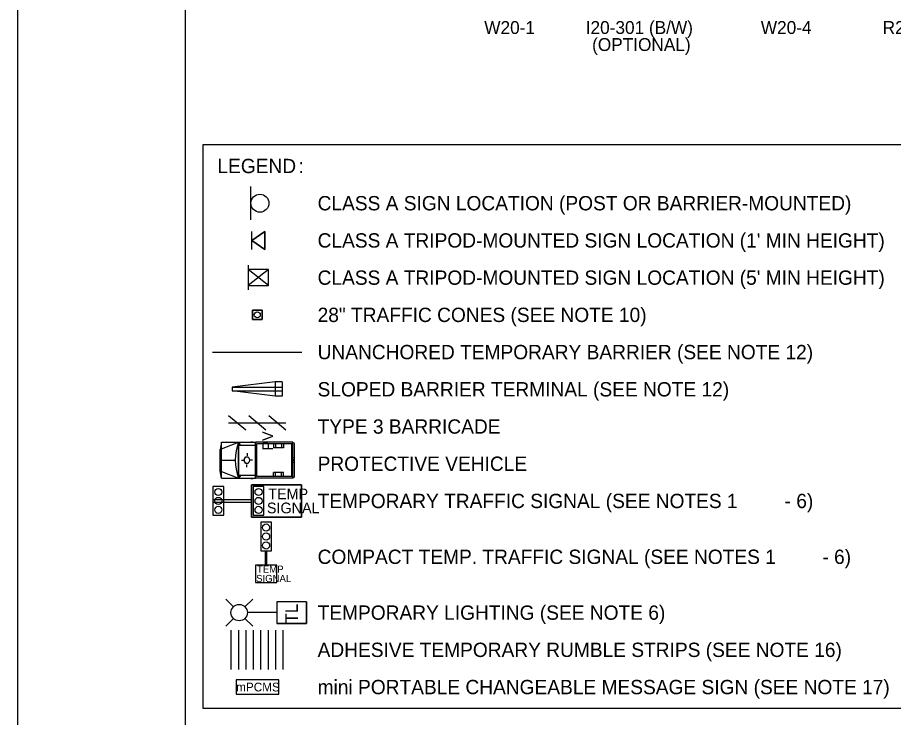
# Model space of a CAD drawing. Extents: x 99977 to 100176, y 99905 to 100011.
# Drawn here: x 99999.062 to 100003.959, y 99971.176 to 99975.088 of the extents above; entities that cross this region are included whole.
import ezdxf

# ---------------------------------------------------------------- set-up
doc = ezdxf.new("R2010")
doc.units = 0
for name, color, linetype in [('SH_GI_PlotLimits', 7, 'Continuous'), ('SH_GI_SheetBorder', 7, 'Continuous'), ('TR_SN_ConstructionSigns', 7, 'Continuous'), ('TR_WZ_BarricadeType3', 7, 'Continuous'), ('TR_WZ_BarrierTemp', 7, 'Continuous'), ('TR_WZ_PortableChangeMessageSign', 7, 'Continuous'), ('TR_WZ_PortableLightStandard', 7, 'Continuous'), ('TR_WZ_PortableSignMount5ftMinBlk-Wht', 7, 'Continuous'), ('TR_WZ_PortableSignMountBlk-Wht', 7, 'Continuous'), ('TR_WZ_ProtectiveVehicle', 7, 'Continuous'), ('TR_WZ_ScaleTerminalEndSection', 7, 'Continuous'), ('TR_WZ_Sign', 7, 'Continuous'), ('TR_WZ_TempSignal', 7, 'Continuous'), ('TR_WZ_TrafficCone', 7, 'Continuous'), ('TR_WZ_WorkZoneDetails', 7, 'Continuous'), ('TR_WZ_WorkZoneTextCurrent', 7, 'Continuous')]:
    doc.layers.add(name, color=color, linetype=linetype)

msp = doc.modelspace()

# ---------------------------------------------------------------- linework, layer by layer
at = {"layer": 'SH_GI_PlotLimits'}
msp.add_lwpolyline([(99999.0625, 99969.6875), (100016.0625, 99969.6875), (100016.0625, 99980.6875), (99999.0625, 99980.6875)], close=True, dxfattribs=at)
at = {"layer": 'SH_GI_SheetBorder'}
msp.add_line((100000, 99980.375), (100000, 99970), dxfattribs=at)
at = {"layer": 'TR_WZ_BarricadeType3'}
for p, q in [((100000.3381, 99972.7823), (100000.2425, 99972.8615)), ((100000.4503, 99972.7823), (100000.3547, 99972.8615)), ((100000.5625, 99972.7823), (100000.4669, 99972.8615)), ((100000.2425, 99972.8219), (100000.5625, 99972.8219))]:
    msp.add_line(p, q, dxfattribs=at)
at = {"layer": 'TR_WZ_BarrierTemp'}
msp.add_line((100000.1525, 99973.2179), (100000.6525, 99973.2179), dxfattribs=at)
at = {"layer": 'TR_WZ_PortableChangeMessageSign'}
msp.add_lwpolyline([(100000.2841, 99971.3059), (100000.5241, 99971.3059), (100000.5241, 99971.3859), (100000.2841, 99971.3859)], close=True, dxfattribs=at)
msp.add_lwpolyline([(100000.2841, 99971.3059), (100000.5241, 99971.3059), (100000.5241, 99971.3859), (100000.2841, 99971.3859), (100000.2841, 99971.3059)], dxfattribs=at)
at = {"layer": 'TR_WZ_PortableLightStandard'}
for p, q in [((100000.2692, 99971.7943), (100000.2261, 99971.8373)), ((100000.3339, 99971.7943), (100000.377, 99971.8373)), ((100000.6777, 99971.8219), (100000.5117, 99971.8219)), ((100000.5117, 99971.8219), (100000.5117, 99971.7019)), ((100000.6777, 99971.8219), (100000.5117, 99971.8219)), ((100000.6777, 99971.8219), (100000.6777, 99971.7019)), ((100000.2692, 99971.7295), (100000.2261, 99971.6864)), ((100000.3339, 99971.7295), (100000.377, 99971.6864)), ((100000.5117, 99971.7619), (100000.3473, 99971.7619)), ((100000.6777, 99971.7019), (100000.5117, 99971.7019)), ((100000.5117, 99971.7019), (100000.6777, 99971.7019))]:
    msp.add_line(p, q, dxfattribs=at)
for points in [[(100000.5117, 99971.8219), (100000.5117, 99971.7619), (100000.5117, 99971.7019)], [(100000.6777, 99971.7019), (100000.6777, 99971.7619), (100000.6777, 99971.8219)]]:
    msp.add_lwpolyline(points, dxfattribs=at)
msp.add_circle((100000.3015, 99971.7619), 0.0457, dxfattribs=at)
msp.add_circle((100000.3015, 99971.7619), 0.0457, dxfattribs=at)
at = {"layer": 'TR_WZ_PortableSignMount5ftMinBlk-Wht'}
for p, q in [((100000.3512, 99973.7029), (100000.3512, 99973.5649)), ((100000.4663, 99973.5891), (100000.3512, 99973.6787)), ((100000.4663, 99973.6787), (100000.3512, 99973.5891)), ((100000.4088, 99973.6339), (100000.4088, 99973.6339)), ((100000.4089, 99973.6338), (100000.4089, 99973.6338))]:
    msp.add_line(p, q, dxfattribs=at)
msp.add_lwpolyline([(100000.4663, 99973.5891), (100000.4663, 99973.6787), (100000.3512, 99973.6787), (100000.3512, 99973.5891)], close=True, dxfattribs=at)
at = {"layer": 'TR_WZ_PortableSignMountBlk-Wht'}
msp.add_line((100000.3728, 99973.7919), (100000.3728, 99973.8919), dxfattribs=at)
msp.add_lwpolyline([(100000.3728, 99973.8418), (100000.4447, 99973.8919), (100000.4447, 99973.7919)], close=True, dxfattribs=at)
at = {"layer": 'TR_WZ_ProtectiveVehicle'}
for p, q in [((100000.2036, 99972.7139), (100000.1944, 99972.6735)), ((100000.2036, 99972.5139), (100000.2036, 99972.7139)), ((100000.2036, 99972.7139), (100000.3925, 99972.7139)), ((100000.2036, 99972.6773), (100000.2981, 99972.7139)), ((100000.2981, 99972.5139), (100000.2981, 99972.7139)), ((100000.2998, 99972.5139), (100000.2998, 99972.7139)), ((100000.3098, 99972.6984), (100000.2998, 99972.7139)), ((100000.3668, 99972.7167), (100000.3781, 99972.7167)), ((100000.3925, 99972.5139), (100000.3925, 99972.7139)), ((100000.601, 99972.7139), (100000.3953, 99972.7139)), ((100000.3953, 99972.5139), (100000.3953, 99972.7139)), ((100000.5952, 99972.7059), (100000.4011, 99972.7059)), ((100000.4011, 99972.5219), (100000.4011, 99972.7059)), ((100000.4938, 99972.7059), (100000.4938, 99972.6829)), ((100000.5038, 99972.7059), (100000.5038, 99972.6829)), ((100000.5378, 99972.7059), (100000.5378, 99972.6829)), ((100000.5488, 99972.7059), (100000.5488, 99972.6829)), ((100000.5952, 99972.5219), (100000.5952, 99972.7059)), ((100000.601, 99972.5139), (100000.601, 99972.7139)), ((100000.6061, 99972.7106), (100000.6017, 99972.7106)), ((100000.6017, 99972.5172), (100000.6017, 99972.7106)), ((100000.1944, 99972.5543), (100000.1944, 99972.6735)), ((100000.2998, 99972.6984), (100000.3925, 99972.6984)), ((100000.5488, 99972.6829), (100000.4938, 99972.6829)), ((100000.6106, 99972.5233), (100000.6106, 99972.7045)), ((100000.2036, 99972.6139), (100000.2795, 99972.6139)), ((100000.315, 99972.6138), (100000.3276, 99972.6138)), ((100000.3458, 99972.6524), (100000.3455, 99972.6373)), ((100000.3592, 99972.6142), (100000.3592, 99972.6142)), ((100000.376, 99972.6147), (100000.3611, 99972.6143)), ((100000.6106, 99972.628), (100000.6017, 99972.6242)), ((100000.6082, 99972.6139), (100000.6041, 99972.6139)), ((100000.6061, 99972.6111), (100000.6061, 99972.6167)), ((100000.3451, 99972.5743), (100000.3451, 99972.5904)), ((100000.6106, 99972.5998), (100000.6017, 99972.6036)), ((100000.2036, 99972.5139), (100000.1944, 99972.5543)), ((100000.2036, 99972.5505), (100000.2981, 99972.5139)), ((100000.2036, 99972.5139), (100000.3925, 99972.5139)), ((100000.2998, 99972.5139), (100000.3118, 99972.5294)), ((100000.2998, 99972.5294), (100000.3925, 99972.5294)), ((100000.3668, 99972.5111), (100000.3781, 99972.5111)), ((100000.601, 99972.5139), (100000.3953, 99972.5139)), ((100000.5952, 99972.5219), (100000.4011, 99972.5219)), ((100000.5488, 99972.5449), (100000.4938, 99972.5449)), ((100000.4938, 99972.5219), (100000.4938, 99972.5449)), ((100000.5038, 99972.5219), (100000.5038, 99972.5449)), ((100000.5378, 99972.5219), (100000.5378, 99972.5449)), ((100000.5488, 99972.5219), (100000.5488, 99972.5449)), ((100000.6061, 99972.5172), (100000.6017, 99972.5172))]:
    msp.add_line(p, q, dxfattribs=at)
for centre, major_axis, start_param, end_param in [((100000.4331, 99972.6139), (0, -0.2099), 4.215852, 5.209111), ((100000.6061, 99972.7045), (0, 0.0061), 4.712389, 6.283185), ((100000.6061, 99972.5233), (0, -0.0061), 6.283185, 7.853982)]:
    msp.add_ellipse(centre, major_axis=major_axis, ratio=0.73155, start_param=start_param, end_param=end_param, dxfattribs=at)
for centre, major_axis in [((100000.3451, 99972.6139), (0, 0.0193)), ((100000.6061, 99972.6139), (0, 0.00282))]:
    msp.add_ellipse(centre, major_axis=major_axis, ratio=0.73155, dxfattribs=at)
at = {"layer": 'TR_WZ_ScaleTerminalEndSection'}
for p, q in [((100000.5025, 99973.051), (100000.2625, 99973.021)), ((100000.5025, 99973.051), (100000.5025, 99972.971)), ((100000.5425, 99973.051), (100000.5025, 99973.051)), ((100000.5425, 99973.051), (100000.5425, 99972.971)), ((100000.2625, 99973.021), (100000.5425, 99973.021)), ((100000.2625, 99973.021), (100000.2625, 99973.001)), ((100000.2625, 99973.001), (100000.5425, 99973.001)), ((100000.5025, 99972.971), (100000.2625, 99973.001)), ((100000.5425, 99972.971), (100000.5025, 99972.971))]:
    msp.add_line(p, q, dxfattribs=at)
at = {"layer": 'TR_WZ_Sign'}
msp.add_line((100000.3668, 99973.9567), (100000.3668, 99974.1431), dxfattribs=at)
msp.add_circle((100000.4172, 99974.05), 0.0504, dxfattribs=at)
msp.add_circle((100000.4172, 99974.05), 0.0504, dxfattribs=at)
at = {"layer": 'TR_WZ_TempSignal'}
for p, q in [((100000.215, 99972.4658), (100000.1551, 99972.4658)), ((100000.1551, 99972.4658), (100000.1551, 99972.306)), ((100000.215, 99972.306), (100000.215, 99972.4658)), ((100000.3701, 99972.4759), (100000.6501, 99972.4759)), ((100000.3701, 99972.2959), (100000.3701, 99972.4759)), ((100000.6501, 99972.4759), (100000.3701, 99972.4759)), ((100000.3701, 99972.4759), (100000.3701, 99972.3926)), ((100000.44, 99972.4658), (100000.3801, 99972.4658)), ((100000.3801, 99972.4658), (100000.3801, 99972.306)), ((100000.44, 99972.306), (100000.44, 99972.4658)), ((100000.6501, 99972.4759), (100000.6501, 99972.2959)), ((100000.6501, 99972.2959), (100000.6501, 99972.4759)), ((100000.3701, 99972.3926), (100000.1551, 99972.3926)), ((100000.1551, 99972.3926), (100000.1551, 99972.3792)), ((100000.1551, 99972.3792), (100000.3701, 99972.3792)), ((100000.3701, 99972.3792), (100000.3701, 99972.3926)), ((100000.3701, 99972.3926), (100000.3701, 99972.3792)), ((100000.3701, 99972.3792), (100000.3701, 99972.2959)), ((100000.1551, 99972.306), (100000.215, 99972.306)), ((100000.6501, 99972.2959), (100000.3701, 99972.2959)), ((100000.3701, 99972.2959), (100000.6501, 99972.2959)), ((100000.3801, 99972.306), (100000.44, 99972.306)), ((100000.4819, 99972.2672), (100000.422, 99972.2672)), ((100000.422, 99972.2672), (100000.422, 99972.1075)), ((100000.4819, 99972.1075), (100000.4819, 99972.2672)), ((100000.422, 99972.1075), (100000.4819, 99972.1075)), ((100000.5119, 99972.0275), (100000.3919, 99972.0275)), ((100000.3919, 99972.0275), (100000.3919, 99971.983)), ((100000.5119, 99971.9297), (100000.5119, 99972.0275)), ((100000.3919, 99971.983), (100000.3919, 99971.9742)), ((100000.3919, 99971.9742), (100000.3919, 99971.9297)), ((100000.3919, 99971.9297), (100000.5119, 99971.9297))]:
    msp.add_line(p, q, dxfattribs=at)
for points in [[(100000.215, 99972.4658), (100000.1551, 99972.4658), (100000.1551, 99972.306), (100000.215, 99972.306), (100000.215, 99972.4658)], [(100000.44, 99972.4658), (100000.3801, 99972.4658), (100000.3801, 99972.306), (100000.44, 99972.306), (100000.44, 99972.4658)], [(100000.4819, 99972.2672), (100000.422, 99972.2672), (100000.422, 99972.1075), (100000.4819, 99972.1075), (100000.4819, 99972.2672)], [(100000.5119, 99972.0275), (100000.3919, 99972.0275), (100000.3919, 99971.9297), (100000.5119, 99971.9297), (100000.5119, 99972.0275)]]:
    msp.add_lwpolyline(points, dxfattribs=at)
msp.add_lwpolyline([(100000.4494, 99972.1075), (100000.4544, 99972.1075), (100000.4544, 99972.0275), (100000.4494, 99972.0275)], close=True, dxfattribs=at)
for centre in [(100000.1851, 99972.4358), (100000.1851, 99972.4358), (100000.4101, 99972.4358), (100000.4101, 99972.4358), (100000.1851, 99972.3859), (100000.1851, 99972.3859), (100000.4101, 99972.3859), (100000.4101, 99972.3859), (100000.1851, 99972.336), (100000.1851, 99972.336), (100000.4101, 99972.336), (100000.4101, 99972.336), (100000.4519, 99972.2373), (100000.4519, 99972.2373), (100000.4519, 99972.1874), (100000.4519, 99972.1874), (100000.4519, 99972.1374), (100000.4519, 99972.1374)]:
    msp.add_circle(centre, 0.02, dxfattribs=at)
at = {"layer": 'TR_WZ_TrafficCone'}
for points in [[(100000.3759, 99973.4526), (100000.4293, 99973.4526), (100000.4293, 99973.3992), (100000.3759, 99973.3992), (100000.3759, 99973.4526)], [(100000.3759, 99973.3992), (100000.4293, 99973.3992), (100000.4293, 99973.4526), (100000.3759, 99973.4526), (100000.3759, 99973.3992)]]:
    msp.add_lwpolyline(points, dxfattribs=at)
msp.add_circle((100000.4026, 99973.4259), 0.0167, dxfattribs=at)
at = {"layer": 'TR_WZ_WorkZoneDetails'}
for p, q in [((100000.2574, 99971.4439), (100000.2574, 99971.6639)), ((100000.2991, 99971.4439), (100000.2991, 99971.6639)), ((100000.3403, 99971.4439), (100000.3403, 99971.6639)), ((100000.382, 99971.4439), (100000.382, 99971.6639)), ((100000.4232, 99971.4439), (100000.4232, 99971.6639)), ((100000.4649, 99971.4439), (100000.4649, 99971.6639)), ((100000.5061, 99971.4439), (100000.5061, 99971.6639)), ((100000.5478, 99971.4439), (100000.5478, 99971.6639))]:
    msp.add_line(p, q, dxfattribs=at)
msp.add_lwpolyline([(100000.4447, 99973.7919), (100000.4447, 99973.8919), (100000.3728, 99973.8418), (100000.4447, 99973.7919)], dxfattribs=at)
at = {"layer": 'TR_WZ_WorkZoneTextCurrent'}
msp.add_lwpolyline([(100000.1, 99974.3779), (100004.1384, 99974.3779), (100004.1384, 99971.2259), (100000.1, 99971.2259)], close=True, dxfattribs=at)

# ---------------------------------------------------------------- texts
at = {"layer": 'TR_SN_ConstructionSigns'}
for s, p in [('W20-1', (100001.6717, 99974.9956)), ('I20-301 (B/W)', (100002.2389, 99974.9956)), ('W20-4', (100003.2176, 99974.9956)), ('R2-1 (B/W)', (100003.8988, 99974.9956)), ('(OPTIONAL)', (100002.2744, 99974.9005))]:
    msp.add_text(s, height=0.072, rotation=360, dxfattribs=at).set_placement(p)
at = {"layer": 'TR_WZ_PortableChangeMessageSign'}
msp.add_text('mPCMS', height=0.04909, rotation=360, dxfattribs=at).set_placement((100000.2845, 99971.3214))
at = {"layer": 'TR_WZ_PortableLightStandard'}
msp.add_text('TL', height=0.07, rotation=90, dxfattribs=at).set_placement((100000.6297, 99971.7017))
at = {"layer": 'TR_WZ_ProtectiveVehicle'}
msp.add_text('PV', height=0.06, rotation=90, dxfattribs=at).set_placement((100000.4913, 99972.6677))
at = {"layer": 'TR_WZ_TempSignal'}
for s, height, p in [('TEMP', 0.06, (100000.4641, 99972.3949)), ('SIGNAL', 0.06, (100000.4567, 99972.3169)), ('TEMP', 0.04, (100000.4013, 99971.9846)), ('SIGNAL', 0.04, (100000.3963, 99971.9326))]:
    msp.add_text(s, height=height, dxfattribs=at).set_placement(p)
at = {"layer": 'TR_WZ_WorkZoneTextCurrent'}
for s, p in [('LEGEND', (100000.18, 99974.2179)), (':', (100000.6328, 99974.2179)), ('CLASS A SIGN LOCATION (POST OR BARRIER-MOUNTED)', (100000.74, 99974.0099)), ("CLASS A TRIPOD-MOUNTED SIGN LOCATION (1' MIN HEIGHT)", (100000.74, 99973.8019)), ("CLASS A TRIPOD-MOUNTED SIGN LOCATION (5' MIN HEIGHT)", (100000.74, 99973.5939)), ('28" TRAFFIC CONES (SEE NOTE 10)', (100000.74, 99973.3859)), ('UNANCHORED TEMPORARY BARRIER (SEE NOTE 12)', (100000.74, 99973.1779)), ('SLOPED BARRIER TERMINAL (SEE NOTE 12)', (100000.74, 99972.9699)), ('TYPE 3 BARRICADE', (100000.74, 99972.7619)), ('PROTECTIVE VEHICLE', (100000.74, 99972.5539)), ('TEMPORARY TRAFFIC SIGNAL (SEE NOTES 1', (100000.74, 99972.3459)), ('- 6)', (100003.3504, 99972.3459)), ('COMPACT TEMP. TRAFFIC SIGNAL (SEE NOTES 1', (100000.74, 99972.0339)), ('- 6)', (100003.5616, 99972.0339)), ('TEMPORARY LIGHTING (SEE NOTE 6)', (100000.74, 99971.7219)), ('ADHESIVE TEMPORARY RUMBLE STRIPS (SEE NOTE 16)', (100000.74, 99971.5139)), ('mini PORTABLE CHANGEABLE MESSAGE SIGN (SEE NOTE 17)', (100000.74, 99971.3059))]:
    msp.add_text(s, height=0.08, rotation=360, dxfattribs=at).set_placement(p)

doc.saveas('drawing.dxf')
